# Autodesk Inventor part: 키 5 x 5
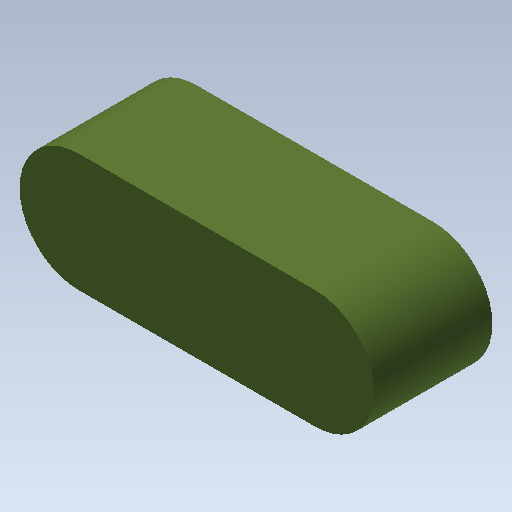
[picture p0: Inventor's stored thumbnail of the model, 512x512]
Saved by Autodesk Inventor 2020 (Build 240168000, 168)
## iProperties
Created: 2011-04
Part Number: 키 5 x 5
Document SubType Name: Modeling
Designer: pww
Density: 7.86 g/cm^3
Material: 강철, 연강
Appearance: 올리브 녹색
Author: pww
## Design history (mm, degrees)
sketch "스케치1"
  geometry: L1 (-5, -2.5)-(5, -2.5); L2 (5, 2.5)-(-5, 2.5); A1 r 2.5 centre (-5, 0) between (-5, 2.5) and (-5, -2.5); A2 r 2.5 centre (5, 0) between (5, -2.5) and (5, 2.5); 1 further point
  constraints: 4 end point, 4 point on circle, 2 centre point
extrude "돌출1" new body sketch "스케치1" distance "d0" = 5; taper "d1" = 0 deg
node "솔리드1"
